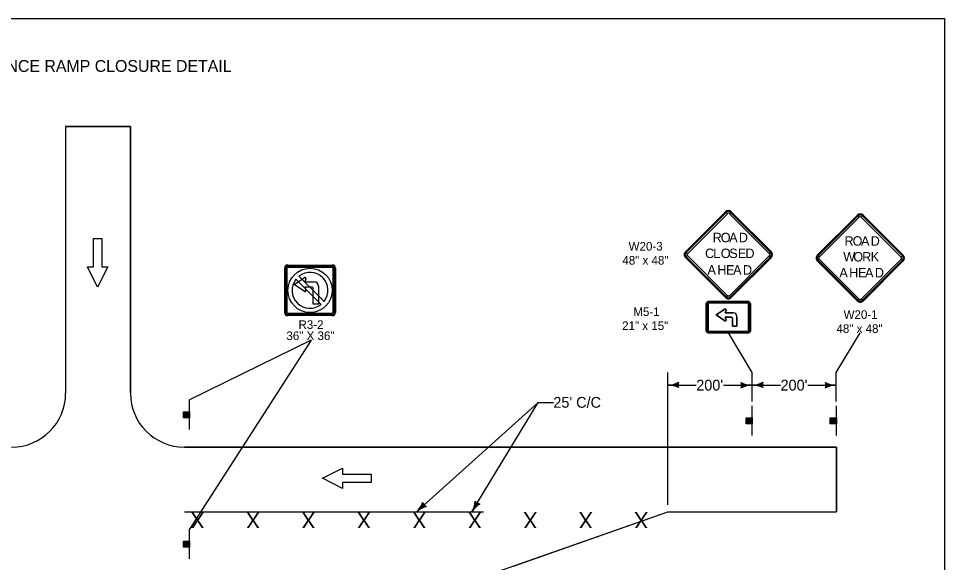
# Model space of a CAD drawing. Extents: x 10133 to 81668, y 7924 to 11018.
# Drawn here: x 11553 to 13268, y 8935 to 9944 of the extents above; entities that cross this region are included whole.
import ezdxf

# ---------------------------------------------------------------- set-up
doc = ezdxf.new("R2010")
doc.units = 0
for name, color, linetype in [('dsnStdBlock', 7, 'Continuous'), ('dsnStdBlockModified', 7, 'Continuous'), ('dsnstdModifiedBlock', 7, 'Continuous')]:
    doc.layers.add(name, color=color, linetype=linetype)

msp = doc.modelspace()

# ---------------------------------------------------------------- linework, layer by layer
at = {"layer": 'dsnStdBlock'}
for p, q in [((11640, 9744), (11760, 9744)), ((12911.1, 9287.6), (12867.4, 9361)), ((13067.2, 9287.6), (13111.6, 9361)), ((12755, 9042.3), (12755, 9287.6)), ((12911.1, 9234.2), (12911.1, 9287.6)), ((13067.2, 9234.2), (13067.2, 9287.6)), ((12755, 9264.2), (12774.2, 9264.6)), ((12755, 9264.2), (12764.7, 9264.4)), ((12755, 9264.2), (12807.8, 9264.2)), ((12858.4, 9264.2), (12911.1, 9264.2)), ((12911.1, 9264.2), (12891.9, 9263.9)), ((12911.1, 9264.2), (12901.4, 9264.1)), ((12911.1, 9264.2), (12930.3, 9264.6)), ((12911.1, 9264.2), (12920.8, 9264.4)), ((12911.1, 9264.2), (12963.9, 9264.2)), ((13014.5, 9264.2), (13067.2, 9264.2)), ((13067.2, 9264.2), (13048, 9263.9)), ((13067.2, 9264.2), (13057.5, 9264.1)), ((11869.3, 9182), (11869.3, 9237)), ((12911.4, 9171), (12911.4, 9226)), ((13067.5, 9171), (13067.5, 9226)), ((11858.7, 9203.7), (11858.7, 9214.9)), ((11859.4, 9214.9), (11859.4, 9203.7)), ((11859.8, 9203.7), (11859.8, 9214.9)), ((11860.5, 9214.9), (11860.5, 9203.7)), ((11860.9, 9203.7), (11860.9, 9214.9)), ((11861.7, 9214.9), (11861.8, 9203.7)), ((11862.2, 9203.7), (11862.2, 9214.9)), ((11863, 9214.9), (11863, 9203.7)), ((11863.8, 9203.7), (11863.8, 9214.9)), ((11864.4, 9214.9), (11864.5, 9203.7)), ((11864.9, 9203.7), (11864.9, 9214.9)), ((11865.4, 9214.9), (11865.4, 9203.7)), ((11866.1, 9203.7), (11866.1, 9214.9)), ((11866.5, 9214.9), (11866.5, 9203.7)), ((11866.9, 9203.7), (11866.9, 9214.9)), ((11867.4, 9214.9), (11867.4, 9203.7)), ((11868, 9203.7), (11868, 9214.9)), ((11868.5, 9214.9), (11868.5, 9203.7)), ((12900.8, 9192.7), (12900.8, 9203.9)), ((12901.5, 9203.9), (12901.5, 9192.7)), ((12901.9, 9192.7), (12901.9, 9203.9)), ((12902.6, 9203.9), (12902.6, 9192.7)), ((12903, 9192.7), (12903, 9203.9)), ((12903.8, 9203.9), (12903.9, 9192.7)), ((12904.3, 9192.7), (12904.3, 9203.9)), ((12905.1, 9203.9), (12905.1, 9192.7)), ((12905.9, 9192.7), (12905.9, 9203.9)), ((12906.5, 9203.9), (12906.5, 9192.7)), ((12907, 9192.7), (12907, 9203.9)), ((12907.5, 9203.9), (12907.5, 9192.7)), ((12908.1, 9192.7), (12908.1, 9203.9)), ((12908.6, 9203.9), (12908.6, 9192.7)), ((12909, 9192.7), (12909, 9203.9)), ((12909.5, 9203.9), (12909.5, 9192.7)), ((12910.1, 9192.7), (12910.1, 9203.9)), ((12910.6, 9203.9), (12910.6, 9192.7)), ((13056.9, 9192.7), (13056.9, 9203.9)), ((13057.6, 9203.9), (13057.6, 9192.7)), ((13058, 9192.7), (13058, 9203.9)), ((13058.6, 9203.9), (13058.6, 9192.7)), ((13059.1, 9192.7), (13059.1, 9203.9)), ((13059.9, 9203.9), (13060, 9192.7)), ((13060.4, 9192.7), (13060.4, 9203.9)), ((13061.2, 9203.9), (13061.2, 9192.7)), ((13062, 9192.7), (13062, 9203.9)), ((13062.6, 9203.9), (13062.6, 9192.7)), ((13063, 9192.7), (13063, 9203.9)), ((13063.6, 9203.9), (13063.6, 9192.7)), ((13064.2, 9192.7), (13064.2, 9203.9)), ((13064.7, 9203.9), (13064.7, 9192.7)), ((13065.1, 9192.7), (13065.1, 9203.9)), ((13065.6, 9203.9), (13065.6, 9192.7)), ((13066.1, 9192.7), (13066.1, 9203.9)), ((13066.7, 9203.9), (13066.7, 9192.7)), ((13067.5, 9149.3), (13067.5, 9029.3)), ((12289.7, 9029.3), (12304, 9042.2)), ((12392.4, 9029.3), (12402.3, 9045.7)), ((12392.4, 9029.3), (12397.4, 9037.6)), ((12289.7, 9029.3), (12296.9, 9035.8)), ((11869.3, 8942), (11869.3, 8997)), ((11858.7, 8963.7), (11858.7, 8974.9)), ((11859.4, 8974.9), (11859.4, 8963.7)), ((11859.8, 8963.7), (11859.8, 8974.9)), ((11860.5, 8974.9), (11860.5, 8963.7)), ((11860.9, 8963.7), (11860.9, 8974.9)), ((11861.7, 8974.9), (11861.8, 8963.7)), ((11862.2, 8963.7), (11862.2, 8974.9)), ((11863, 8974.9), (11863, 8963.7)), ((11863.8, 8963.7), (11863.8, 8974.9)), ((11864.4, 8974.9), (11864.5, 8963.7)), ((11864.9, 8963.7), (11864.9, 8974.9)), ((11865.4, 8974.9), (11865.4, 8963.7)), ((11866.1, 8963.7), (11866.1, 8974.9)), ((11866.5, 8974.9), (11866.5, 8963.7)), ((11866.9, 8963.7), (11866.9, 8974.9)), ((11867.4, 8974.9), (11867.4, 8963.7)), ((11868, 8963.7), (11868, 8974.9)), ((11868.5, 8974.9), (11868.5, 8963.7))]:
    msp.add_line(p, q, dxfattribs=at)
for points in [[(11760, 9249.3), (11760, 9744), (11640, 9744), (11640, 9249.3)], [(11706.8, 9483.4), (11718.1, 9483.4), (11699.3, 9445.9), (11680.6, 9483.4), (11691.8, 9483.4), (11691.8, 9535.9), (11706.8, 9535.9), (11706.8, 9483.4)], [(12773.8, 9268.1), (12773.1, 9264.5), (12773.9, 9261), (12769.6, 9262.9), (12762.8, 9264.4), (12770.1, 9266.2), (12773.2, 9267.7), (12772.5, 9264.5), (12772.8, 9262.2), (12770, 9263.5), (12766.2, 9264.4), (12770.2, 9265.7), (12772.3, 9266.4), (12771.9, 9263.4), (12769.1, 9264.5), (12771.3, 9265.2), (12771.3, 9264.2), (12770.3, 9264.5)], [(12892.4, 9260.4), (12893, 9263.9), (12892.2, 9267.5), (12896.5, 9265.5), (12903.4, 9264.1), (12896.1, 9262.3), (12893, 9260.8), (12893.7, 9264), (12893.3, 9266.3), (12896.2, 9265), (12900, 9264.1), (12896, 9262.8), (12893.9, 9262.1), (12894.2, 9265.1), (12897, 9264), (12894.9, 9263.3), (12894.8, 9264.3), (12895.8, 9264)], [(12929.9, 9268.1), (12929.2, 9264.5), (12930, 9261), (12925.7, 9262.9), (12918.9, 9264.4), (12926.2, 9266.2), (12929.3, 9267.7), (12928.6, 9264.5), (12928.9, 9262.2), (12926.1, 9263.5), (12922.3, 9264.4), (12926.3, 9265.7), (12928.4, 9266.4), (12928, 9263.4), (12925.2, 9264.5), (12927.4, 9265.2), (12927.4, 9264.2), (12926.4, 9264.5)], [(13048.5, 9260.4), (13049.1, 9263.9), (13048.3, 9267.5), (13052.6, 9265.5), (13059.5, 9264.1), (13052.2, 9262.3), (13049, 9260.8), (13049.8, 9264), (13049.4, 9266.3), (13052.3, 9265), (13056.1, 9264.1), (13052.1, 9262.8), (13050, 9262.1), (13050.3, 9265.1), (13053.1, 9264), (13051, 9263.3), (13050.9, 9264.3), (13051.9, 9264)], [(12469.1, 8928.8), (12755.3, 9029.3), (13067.5, 9029.3), (13067.5, 9149.3), (11860, 9149.3)], [(12153, 9084), (12153, 9072.8), (12115.5, 9091.5), (12153, 9110.3), (12153, 9099), (12205.5, 9099), (12205.5, 9084), (12153, 9084)], [(12301.3, 9044.5), (12303.1, 9041.4), (12306.1, 9039.2), (12301.5, 9037.9), (12295.4, 9034.5), (12299.7, 9040.6), (12301.1, 9043.8), (12302.7, 9041), (12304.4, 9039.4), (12301.4, 9038.6), (12298, 9036.7), (12300.2, 9040.3), (12301.2, 9042.2), (12303, 9039.7), (12300.2, 9038.7), (12301.3, 9040.7), (12302, 9039.9), (12301.1, 9039.5)], [(12399, 9047.2), (12401.7, 9044.8), (12405.2, 9043.5), (12401.2, 9040.9), (12396.4, 9035.9), (12398.7, 9043.1), (12399.1, 9046.5), (12401.4, 9044.2), (12403.5, 9043.3), (12400.9, 9041.5), (12398.1, 9038.8), (12399.2, 9042.8), (12399.7, 9045), (12402.1, 9043.1), (12399.6, 9041.3), (12400.2, 9043.6), (12401.1, 9043), (12400.3, 9042.3)]]:
    msp.add_lwpolyline(points, dxfattribs=at)
for points in [[(11869.2, 9214.9), (11869.2, 9203.6), (11858, 9203.6), (11858, 9214.9)], [(12911.2, 9203.9), (12911.2, 9192.6), (12900.1, 9192.6), (12900.1, 9203.9)], [(13067.3, 9203.9), (13067.3, 9192.6), (13056.1, 9192.6), (13056.1, 9203.9)], [(11869.2, 8974.9), (11869.2, 8963.6), (11858, 8963.6), (11858, 8974.9)]]:
    msp.add_lwpolyline(points, close=True, dxfattribs=at)
for centre, radius, start, end in [((12754.3, 9306.7), 42.5, 271, 299.0725), ((12755.8, 9221.8), 42.5, 62.9275, 91), ((12790.7, 9264.9), 16.4, 163.2666, 198.7334), ((12910.4, 9306.7), 42.5, 242.9275, 271), ((12875.5, 9263.6), 16.4, 343.2666, 18.7334), ((12911.9, 9221.8), 42.5, 91, 119.0725), ((12910.4, 9306.7), 42.5, 271, 299.0725), ((12911.9, 9221.8), 42.5, 62.9275, 91), ((12946.8, 9264.9), 16.4, 163.2666, 198.7334), ((13066.5, 9306.7), 42.5, 242.9275, 271), ((13031.6, 9263.6), 16.4, 343.2666, 18.7334), ((13068, 9221.8), 42.5, 91, 119.0725), ((11540, 9249.3), 100, 270, 0), ((11860, 9249.3), 100, 180, 270), ((12261.2, 9060.9), 42.5, 312.025, 340.0975), ((12318.1, 8997.7), 42.5, 103.9525, 132.025), ((12316.2, 9053.2), 16.4, 204.2917, 239.7584), ((12356, 9051.3), 42.5, 328.8429, 356.9154), ((12428.7, 9007.3), 42.5, 120.7705, 148.8429), ((12410.8, 9059.8), 16.4, 221.1096, 256.5763)]:
    msp.add_arc(centre, radius, start, end, dxfattribs=at)
at = {"layer": 'dsnStdBlockModified'}
for p, q in [((12862.1, 9585.7), (12787.8, 9511.4)), ((12946.9, 9511.4), (12872.7, 9585.7)), ((12863.4, 9584.3), (12865.6, 9582.1)), ((12869.1, 9582.1), (12871.3, 9584.3)), ((13106.3, 9579.3), (13032, 9505)), ((13107.6, 9577.9), (13109.8, 9575.7)), ((13113.4, 9575.7), (13115.6, 9577.9)), ((13191.1, 9505), (13116.9, 9579.3)), ((12787.8, 9500.8), (12862.1, 9426.6)), ((12791.4, 9507.9), (12789.1, 9510.1)), ((12789.1, 9502.1), (12791.4, 9504.3)), ((12872.7, 9426.6), (12946.9, 9500.8)), ((12945.6, 9510.1), (12943.4, 9507.9)), ((12943.4, 9504.3), (12945.6, 9502.1)), ((13035.6, 9501.5), (13033.4, 9503.7)), ((13189.8, 9503.7), (13187.6, 9501.5)), ((12051.6, 9486.9), (12133.7, 9486.9)), ((12051.6, 9485.3), (12133.7, 9485.3)), ((12051.6, 9485.3), (12133.7, 9485.3)), ((12051.6, 9483), (12133.7, 9483)), ((12133.7, 9483), (12051.6, 9483)), ((13032, 9494.4), (13106.3, 9420.2)), ((13033.4, 9495.7), (13035.6, 9498)), ((13116.9, 9420.2), (13191.1, 9494.4)), ((13187.6, 9498), (13189.8, 9495.7)), ((12045.7, 9399), (12045.7, 9481)), ((12047.4, 9399), (12047.4, 9481)), ((12047.4, 9399), (12047.4, 9481)), ((12049.6, 9399), (12049.6, 9481)), ((12049.6, 9481), (12049.6, 9399)), ((12118.7, 9419.4), (12072.1, 9466.1)), ((12135.6, 9481), (12135.6, 9399)), ((12135.6, 9399), (12135.6, 9481)), ((12137.9, 9481), (12137.9, 9399)), ((12137.9, 9481), (12137.9, 9399)), ((12139.5, 9481), (12139.5, 9399)), ((12066.5, 9460.6), (12113.2, 9413.9)), ((12826.5, 9364.6), (12826.5, 9415.7)), ((12826.5, 9415.7), (12826.5, 9364.6)), ((12827.9, 9415.7), (12827.9, 9364.6)), ((12827.9, 9364.6), (12827.9, 9415.7)), ((12829.9, 9364.6), (12829.9, 9415.7)), ((12829.9, 9364.6), (12829.9, 9415.7)), ((12829.9, 9415.7), (12829.9, 9364.6)), ((12831.6, 9419.4), (12903.1, 9419.4)), ((12903.1, 9419.4), (12831.6, 9419.4)), ((12903.1, 9418.4), (12831.6, 9418.4)), ((12831.6, 9418.4), (12903.1, 9418.4)), ((12831.6, 9416.9), (12903.1, 9416.9)), ((12831.6, 9416.9), (12903.1, 9416.9)), ((12903.1, 9416.9), (12831.6, 9416.9)), ((12865.6, 9430.1), (12863.4, 9427.9)), ((12871.3, 9427.9), (12869.1, 9430.1)), ((12904.8, 9415.7), (12904.8, 9364.6)), ((12904.8, 9364.6), (12904.8, 9415.7)), ((12906.8, 9364.6), (12906.8, 9415.7)), ((12906.8, 9415.7), (12906.8, 9364.6)), ((12908.2, 9415.7), (12908.2, 9364.6)), ((12908.2, 9364.6), (12908.2, 9415.7)), ((13109.8, 9423.7), (13107.6, 9421.5)), ((13115.6, 9421.5), (13113.4, 9423.7)), ((12133.7, 9397), (12051.6, 9397)), ((12051.6, 9397), (12133.7, 9397)), ((12133.7, 9394.7), (12051.6, 9394.7)), ((12133.7, 9394.7), (12051.6, 9394.7)), ((12133.7, 9393.1), (12051.6, 9393.1)), ((12903.1, 9363.4), (12831.6, 9363.4)), ((12831.6, 9363.4), (12903.1, 9363.4)), ((12094.8, 9347.8), (11869.3, 9237)), ((12094.8, 9347.8), (11869.3, 8997)), ((12831.6, 9362), (12903.1, 9362)), ((12903.1, 9362), (12831.6, 9362)), ((12903.1, 9361), (12831.6, 9361)), ((12831.6, 9361), (12903.1, 9361)), ((12514.9, 9232.3), (12289.7, 9029.3)), ((12392.4, 9029.3), (12514.9, 9232.3)), ((12514.9, 9232.3), (12543.2, 9232.3))]:
    msp.add_line(p, q, dxfattribs=at)
for points in [[(12863.4, 9584.3), (12789.1, 9510.1), (12791.4, 9507.9), (12865.6, 9582.1), (12863.4, 9584.3)], [(12945.6, 9510.1), (12871.3, 9584.3), (12869.1, 9582.1), (12943.4, 9507.9), (12945.6, 9510.1)], [(13107.6, 9577.9), (13033.4, 9503.7), (13035.6, 9501.5), (13109.8, 9575.7), (13107.6, 9577.9)], [(13189.8, 9503.7), (13115.6, 9577.9), (13113.4, 9575.7), (13187.6, 9501.5), (13189.8, 9503.7)], [(12789.1, 9502.1), (12863.4, 9427.9), (12865.6, 9430.1), (12791.4, 9504.3), (12789.1, 9502.1)], [(12871.3, 9427.9), (12945.6, 9502.1), (12943.4, 9504.3), (12869.1, 9430.1), (12871.3, 9427.9)], [(13033.4, 9495.7), (13107.6, 9421.5), (13109.8, 9423.7), (13035.6, 9498), (13033.4, 9495.7)], [(13115.6, 9421.5), (13189.8, 9495.7), (13187.6, 9498), (13113.4, 9423.7), (13115.6, 9421.5)]]:
    msp.add_lwpolyline(points, close=True, dxfattribs=at)
for points in [[(12082.1, 9437.9), (12063.3, 9450.8), (12082.1, 9463.6)], [(12085, 9461.4), (12083.2, 9455.6), (12100.4, 9455.6)], [(12096.5, 9445.9), (12083.2, 9445.9), (12085, 9440.1)], [(12108.3, 9447.8), (12108.3, 9414.6), (12098.5, 9414.6), (12098.5, 9443.9)], [(12860.7, 9405.4), (12844.6, 9394.4), (12860.7, 9383.3)], [(12860.7, 9383.3), (12844.6, 9394.4), (12860.7, 9405.4)], [(12876.4, 9398.5), (12861.6, 9398.5), (12863.2, 9403.5)], [(12863.2, 9403.5), (12861.6, 9398.5), (12876.4, 9398.5)], [(12863.2, 9385.2), (12861.6, 9390.2), (12873.1, 9390.2)], [(12873.1, 9390.2), (12861.6, 9390.2), (12863.2, 9385.2)], [(12874.8, 9388.5), (12874.8, 9373.3), (12883.1, 9373.3), (12883.1, 9391.8)], [(12883.1, 9391.8), (12883.1, 9373.3), (12874.8, 9373.3), (12874.8, 9388.5)]]:
    msp.add_lwpolyline(points, dxfattribs=at)
msp.add_circle((12092.6, 9440), 41, dxfattribs=at)
for centre, radius, start, end in [((12867.4, 9580.4), 7.5, 45, 134.9997), ((12867.4, 9580.4), 5.62, 45, 134.9997), ((12867.4, 9580.4), 2.5, 45, 134.9997), ((13111.6, 9574), 7.5, 45, 134.9997), ((13111.6, 9574), 5.62, 45, 134.9997), ((13111.6, 9574), 2.5, 45, 134.9997), ((12793.1, 9506.1), 7.5, 134.9997, 225), ((12793.1, 9506.1), 5.62, 134.9997, 225), ((12793.1, 9506.1), 2.5, 134.9997, 225), ((12941.6, 9506.1), 2.5, 315.0002, 44.9998), ((12941.6, 9506.1), 5.62, 315.0002, 44.9998), ((12941.6, 9506.1), 7.5, 315.0002, 44.9998), ((13037.3, 9499.7), 7.5, 134.9997, 225), ((13037.3, 9499.7), 5.62, 134.9997, 225), ((13037.3, 9499.7), 2.5, 134.9997, 225), ((13185.8, 9499.7), 2.5, 315.0002, 44.9998), ((13185.8, 9499.7), 5.62, 315.0002, 44.9998), ((13185.8, 9499.7), 7.5, 315.0002, 44.9998), ((12051.6, 9481), 5.86, 90, 180), ((12051.6, 9481), 4.23, 90, 180), ((12051.6, 9481), 4.23, 90, 180), ((12051.6, 9481), 1.95, 90, 180), ((12051.6, 9481), 1.95, 90, 180), ((12133.7, 9481), 5.86, 0, 90), ((12133.7, 9481), 4.23, 360, 90), ((12133.7, 9481), 4.23, 360, 90), ((12133.7, 9481), 1.95, 360, 90), ((12133.7, 9481), 1.95, 360, 90), ((12092.6, 9440), 33.2, 321.7563, 128.2437), ((12092.6, 9440), 33.2, 141.7563, 308.2437), ((12083.2, 9462), 1.95, 342.0836, 124.4055), ((12100.4, 9447.8), 7.81, 0, 90), ((12083.2, 9439.5), 1.95, 235.5945, 17.9164), ((12096.5, 9443.9), 1.95, 0, 90), ((12867.4, 9431.9), 7.5, 225, 315.0002), ((12867.4, 9431.9), 5.62, 225, 315.0002), ((12867.4, 9431.9), 2.5, 225, 315.0002), ((13111.6, 9425.5), 7.5, 225, 315.0002), ((13111.6, 9425.5), 5.62, 225, 315.0002), ((13111.6, 9425.5), 2.5, 225, 315.0002), ((12051.6, 9399), 5.86, 180, 270), ((12051.6, 9399), 4.23, 180, 270), ((12051.6, 9399), 4.23, 180, 270), ((12051.6, 9399), 1.95, 180, 270), ((12051.6, 9399), 1.95, 180, 270), ((12133.7, 9399), 1.95, 270, 0), ((12133.7, 9399), 4.23, 270, 0), ((12133.7, 9399), 5.86, 270, 0), ((12133.7, 9399), 4.23, 270, 0), ((12133.7, 9399), 1.95, 270, 0), ((12861.6, 9404), 1.68, 342.0836, 124.4055), ((12861.6, 9404), 1.68, 342.0836, 124.4055), ((12876.4, 9391.8), 6.7, 360, 90), ((12876.4, 9391.8), 6.7, 360, 90), ((12861.6, 9384.7), 1.68, 235.5945, 17.9164), ((12861.6, 9384.7), 1.68, 235.5945, 17.9164), ((12873.1, 9388.5), 1.68, 360, 90), ((12873.1, 9388.5), 1.68, 360, 90)]:
    msp.add_arc(centre, radius, start, end, dxfattribs=at)
for centre, major_axis, start_param, end_param in [((12831.6, 9415.7), (-5.11, 0), 4.712389, 6.283185), ((12831.6, 9415.7), (-5.11, 0), 4.712389, 6.283185), ((12831.6, 9415.7), (-3.69, 0), 4.712389, 6.283185), ((12831.6, 9415.7), (-3.69, 0), 4.712389, 6.283185), ((12831.6, 9415.7), (-1.7, 0), 4.712389, 6.283185), ((12831.6, 9415.7), (-1.7, 0), 4.712389, 6.283185), ((12831.6, 9415.7), (-1.7, 0), 4.712389, 6.283185), ((12903.1, 9415.7), (-5.11, 0), 3.141593, 4.712389), ((12903.1, 9415.7), (-5.11, 0), 3.141593, 4.712389), ((12903.1, 9415.7), (-3.69, 0), 3.141593, 4.712389), ((12903.1, 9415.7), (-3.69, 0), 3.141593, 4.712389), ((12903.1, 9415.7), (-1.7, 0), 3.141593, 4.712389), ((12903.1, 9415.7), (-1.7, 0), 3.141593, 4.712389), ((12831.6, 9364.6), (5.11, 0), 3.141593, 4.712389), ((12831.6, 9364.6), (5.11, 0), 3.141593, 4.712389), ((12831.6, 9364.6), (3.69, 0), 3.141593, 4.712389), ((12831.6, 9364.6), (3.69, 0), 3.141593, 4.712389), ((12831.6, 9364.6), (1.7, 0), 3.141593, 4.712389), ((12831.6, 9364.6), (1.7, 0), 3.141593, 4.712389), ((12831.6, 9364.6), (1.7, 0), 3.141593, 4.712389), ((12903.1, 9364.6), (5.11, 0), 4.712389, 6.283185), ((12903.1, 9364.6), (3.69, 0), 4.712389, 6.283185), ((12903.1, 9364.6), (1.7, 0), 4.712389, 6.283185), ((12903.1, 9364.6), (5.11, 0), 4.712389, 6.283185), ((12903.1, 9364.6), (3.69, 0), 4.712389, 6.283185), ((12903.1, 9364.6), (1.7, 0), 4.712389, 6.283185)]:
    msp.add_ellipse(centre, major_axis=major_axis, ratio=0.714286, start_param=start_param, end_param=end_param, dxfattribs=at)
at = {"layer": 'dsnstdModifiedBlock'}
for p, q in [((11640, 9744), (11640, 9249.3)), ((11760, 9744), (11760, 9249.3)), ((11860, 9149.3), (13067.5, 9149.3)), ((11860, 9029.3), (12413.8, 9029.3)), ((12413.8, 8909.3), (12755.3, 9029.3)), ((12755.3, 9029.3), (13067.5, 9029.3))]:
    msp.add_line(p, q, dxfattribs=at)
msp.add_lwpolyline([(10132.5, 9944), (13267.5, 9944), (13267.5, 7924), (10132.5, 7924)], close=True, dxfattribs=at)
for centre, start, end in [((11540, 9249.3), 270, 0), ((11860, 9249.3), 180, 270)]:
    msp.add_arc(centre, 100, start, end, dxfattribs=at)

# ---------------------------------------------------------------- texts
at = {"layer": 'dsnStdBlock'}
msp.add_text('ENTRANCE RAMP CLOSURE DETAIL', height=22, dxfattribs=at).set_placement((11430.7, 9845))
for p in [(11897.8, 9029.3), (12000.5, 9029.3), (12103.1, 9029.3), (12205.8, 9029.3), (12308.5, 9029.3), (12411.2, 9029.3), (12513.9, 9029.3), (12616.6, 9029.3), (12719.3, 9029.3)]:
    msp.add_text('X', height=30, rotation=180, dxfattribs=at).set_placement(p)
at = {"layer": 'dsnStdBlockModified'}
for s, height, p in [('R', 17.5, (12838.2, 9529.2)), ('O', 17.5, (12853.2, 9529.2)), ('A', 17.5, (12868.8, 9529.2)), ('D', 17.5, (12886.7, 9529.2)), ('R', 17.5, (13082.4, 9522.8)), ('O', 17.5, (13097.4, 9522.8)), ('A', 17.5, (13113, 9522.8)), ('D', 17.5, (13130.9, 9522.8)), ('W20-3', 16, (12682.6, 9513.7)), ('C', 17.5, (12824.2, 9499.9)), ('L', 17.5, (12839.3, 9499.9)), ('O', 17.5, (12853.3, 9499.9)), ('S', 17.5, (12868.9, 9499.9)), ('E', 17.5, (12884.8, 9499.9)), ('D', 17.5, (12898.8, 9499.9)), ('48" x 48"', 16, (12671, 9487.7)), ('W', 17.5, (13080.1, 9493.5)), ('O', 17.5, (13098.7, 9493.5)), ('R', 17.5, (13115.1, 9493.5)), ('K', 17.5, (13131, 9493.5)), ('A', 17.5, (12828.6, 9469.2)), ('H', 17.5, (12846.8, 9469.2)), ('E', 17.5, (12863.1, 9469.2)), ('A', 17.5, (12876.1, 9469.2)), ('D', 17.5, (12894.3, 9469.2)), ('A', 17.5, (13072.9, 9464.1)), ('H', 17.5, (13091.1, 9464.1)), ('E', 17.5, (13107.3, 9464.1)), ('A', 17.5, (13120.4, 9464.1)), ('D', 17.5, (13138.6, 9464.1)), ('M5-1', 16, (12691.3, 9392.4)), ('W20-1', 16, (13080.7, 9387)), ('R3-2', 16, (12071.2, 9368.5)), ('21" x 15"', 16, (12670.6, 9366.4)), ('36" X 36"', 16, (12048.9, 9347.8)), ('48" x 48"', 16, (13067.5, 9361)), ("200'", 20, (12807.8, 9254.2)), ("200'", 20, (12963.9, 9254.2)), ("25' C/C", 20, (12543.2, 9222.3))]:
    msp.add_text(s, height=height, dxfattribs=at).set_placement(p)

doc.saveas('drawing.dxf')
